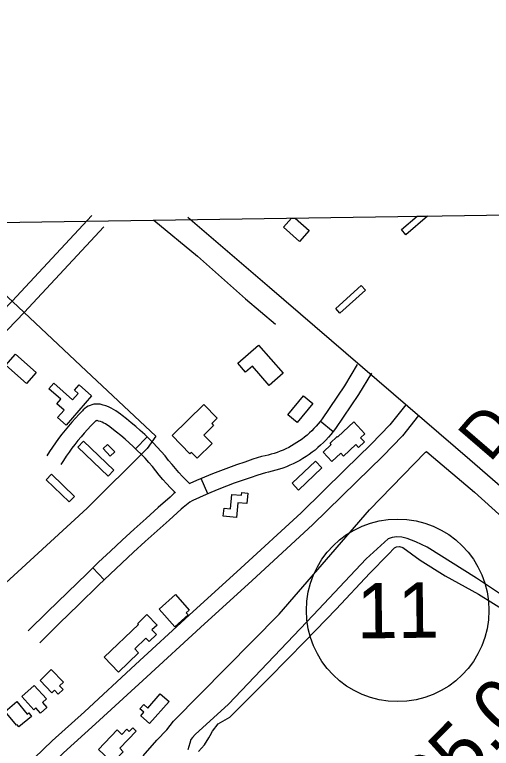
# Model space of a CAD drawing. Extents: x 3823584 to 3861785, y 301729 to 327625.
# Drawn here: x 3835049 to 3835911, y 324501 to 325827 of the extents above; entities that cross this region are included whole.
import ezdxf

# ---------------------------------------------------------------- set-up
doc = ezdxf.new("R2010")
doc.units = 0
for name, color, linetype in [('V-BLDG-OTLN', 7, 'Continuous'), ('V-GRID-FRAM', 7, 'Continuous'), ('V-RIVR-RANG-IDEN', 7, 'Continuous'), ('V-ROAD-CNTR', 7, 'Continuous'), ('V-ROAD-IDEN', 7, 'Continuous'), ('V-SITE-OTLN', 7, 'Continuous'), ('V-SITE-VEGE', 7, 'Continuous'), ('V-SURV-IDEN', 7, 'Continuous'), ('V-TOPO-SHOR', 7, 'Continuous')]:
    doc.layers.add(name, color=color, linetype=linetype)

msp = doc.modelspace()

# ---------------------------------------------------------------- linework, layer by layer
at = {"layer": 'V-BLDG-OTLN'}
for p, q in [((3835534.9, 325442.9), (3835549.4, 325459.3)), ((3835549.4, 325459.3), (3835556, 325459.4)), ((3835556, 325459.4), (3835581.4, 325437)), ((3835748, 325438.5), (3835776.3, 325462.8)), ((3835795, 325463.1), (3835755.9, 325429.4)), ((3835776.3, 325462.8), (3835795, 325463.1)), ((3835563.9, 325417.2), (3835534.9, 325442.9)), ((3835581.4, 325437), (3835563.9, 325417.2)), ((3835755.9, 325429.4), (3835748, 325438.5))]:
    msp.add_line(p, q, dxfattribs=at)
for points in [[(3835682.9, 325329), (3835636.9, 325287.6), (3835629.3, 325296), (3835675.3, 325337.5)], [(3835489.9, 325229.7), (3835534.2, 325179), (3835509.1, 325157.1), (3835479, 325191.6), (3835466.5, 325180.7), (3835452.4, 325196.9)], [(3835050.7, 325213.5), (3835088.1, 325180.5), (3835070.2, 325160.3), (3835032.9, 325193.4)], [(3835188.1, 325138.2), (3835141.8, 325085.4), (3835126.6, 325098.7), (3835138.3, 325112.1), (3835125.2, 325123.6), (3835132.4, 325131.9), (3835110.8, 325150.8), (3835119.6, 325160.9), (3835153.7, 325131), (3835163.7, 325142.5), (3835157.1, 325148.2), (3835165.6, 325157.9)], [(3835588.2, 325124.3), (3835559.7, 325089.7), (3835542.9, 325103.6), (3835571.4, 325138.1)], [(3835333.5, 325066.6), (3835391.1, 325122.3), (3835415.1, 325097.6), (3835405.1, 325088), (3835408.7, 325084.3), (3835391.2, 325067.3), (3835406, 325052), (3835378.6, 325025.4), (3835368.6, 325035.7), (3835365.9, 325033.1)], [(3835661.8, 325091), (3835682.1, 325069.6), (3835674.4, 325062.3), (3835681.3, 325055.1), (3835670.4, 325044.7), (3835665.5, 325049.9), (3835643.6, 325029.2), (3835638.5, 325034.6), (3835622.6, 325019.6), (3835606.6, 325036.5), (3835621.1, 325050.2), (3835619.2, 325052.3), (3835632.2, 325064.6), (3835633, 325063.8)], [(3835173.3, 325056.2), (3835228.5, 325003.7), (3835218.3, 324992.9), (3835163, 325045.4)], [(3835217, 325050.4), (3835229.8, 325036.7), (3835221.7, 325029.2), (3835209, 325042.9)], [(3835604.4, 325008.1), (3835562, 324967.9), (3835550.5, 324980), (3835593, 325020.3)], [(3835115.3, 324996.5), (3835157, 324956.4), (3835147.5, 324946.5), (3835105.7, 324986.6)], [(3835470.3, 324962.2), (3835468.5, 324943.3), (3835452.7, 324944.8), (3835450.2, 324918.4), (3835426, 324920.6), (3835427.4, 324934.9), (3835439.4, 324933.8), (3835441.8, 324959.9), (3835459, 324958.3), (3835459.5, 324963.2)], [(3835339.6, 324778.9), (3835364.7, 324750.9), (3835359.3, 324746), (3835362.7, 324742.1), (3835338.7, 324720.7), (3835310.2, 324752.6)], [(3835273.1, 324673.5), (3835236.8, 324638.9), (3835211, 324665.9), (3835272.9, 324725.1), (3835271.4, 324726.7), (3835288.2, 324742.8), (3835306.3, 324723.9), (3835297.2, 324715.3), (3835305.3, 324706.8), (3835291.9, 324694), (3835286.3, 324699.9), (3835266.2, 324680.7)], [(3835115.2, 324643.4), (3835137.1, 324620.8), (3835130.3, 324614.3), (3835136.7, 324607.6), (3835127.9, 324599), (3835121.1, 324606), (3835116.4, 324601.5), (3835094.8, 324623.7)], [(3835084.4, 324614.8), (3835106.3, 324590.6), (3835099, 324584), (3835107.2, 324574.9), (3835095.9, 324564.7), (3835087.5, 324574.1), (3835083.8, 324570.8), (3835062.2, 324594.6)], [(3835328, 324585.4), (3835292.5, 324545.7), (3835276.8, 324559.8), (3835282.5, 324566.2), (3835275.2, 324572.7), (3835282.2, 324580.5), (3835289.5, 324573.9), (3835312.3, 324599.4)], [(3835053.2, 324585.4), (3835071.7, 324562.9), (3835074.3, 324565.1), (3835079.6, 324558.7), (3835056.7, 324539.9), (3835053.6, 324543.6), (3835052.6, 324542.8), (3835031.9, 324567.9)], [(3835200.4, 324499.1), (3835234.1, 324534.2), (3835242.5, 324526.1), (3835251.8, 324535.8), (3835256.1, 324531.6), (3835262.3, 324538), (3835268.6, 324532), (3835238.9, 324501.1), (3835245.4, 324494.8), (3835230.8, 324479.7), (3835224.6, 324485.7), (3835219.7, 324480.6)]]:
    msp.add_lwpolyline(points, close=True, dxfattribs=at)
at = {"layer": 'V-GRID-FRAM'}
msp.add_lwpolyline([(3827552.2, 325336), (3859397.3, 325827), (3859685.5, 307646.8), (3827824.6, 307155.6), (3827552.2, 325336)], dxfattribs=at)
at = {"layer": 'V-ROAD-CNTR'}
for p, q in [((3835624.6, 325073.2), (3835601.3, 325092.1)), ((3835267.7, 325042.4), (3835288.4, 325064.1)), ((3835398, 324960.9), (3835386.2, 324988.5)), ((3835211, 324805.6), (3835190.2, 324827.2))]:
    msp.add_line(p, q, dxfattribs=at)
for points in [[(3835188.4, 325464.1), (3835044.2, 325309.3), (3834969.1, 325232), (3834950.1, 325209.7)], [(3835362.2, 325460.9), (3835509.5, 325334.3), (3835871.8, 325022.8), (3836108.4, 324817.6), (3836414, 324556.9), (3836839.8, 324193.7), (3837163.7, 323918.8), (3837445, 323669.4), (3837836.5, 323328.4), (3838069.6, 323134.9), (3838125.4, 323086.8), (3838256, 322989.5), (3838600, 322735.4), (3839019.3, 322425.4), (3839565.5, 322022.9), (3840024.9, 321675.2), (3840474.9, 321350), (3840728.4, 321161.3)], [(3835210.4, 325443.7), (3835066, 325288.6), (3834991.3, 325211.8), (3834963.4, 325179), (3834930.6, 325140.4)], [(3835668.4, 325194.8), (3835645.4, 325156.5), (3835604.6, 325096.4), (3835601.2, 325092), (3835597.6, 325087.5), (3835593.9, 325083.2), (3835590, 325079), (3835586, 325075), (3835581.9, 325071), (3835577.6, 325067.2), (3835573.2, 325063.6), (3835568.7, 325060.1), (3835564.1, 325056.8), (3835559.3, 325053.6), (3835554.5, 325050.5), (3835549.6, 325047.7), (3835544.6, 325045), (3835539.4, 325042.4), (3835534.2, 325040.1), (3835529, 325037.9), (3835523.6, 325035.9), (3835518.2, 325034), (3835512.8, 325032.4), (3835507.3, 325030.9), (3835501.7, 325029.6), (3835495.1, 325028.3), (3835479.6, 325023.4), (3835464.8, 325018.5), (3835450.2, 325013.5), (3835435.6, 325008.2), (3835421, 325002.7), (3835406.6, 324997), (3835392.2, 324991.1), (3835377.9, 324985), (3835365.4, 324979.4)], [(3835694.1, 325179.3), (3835670.7, 325140.3), (3835629, 325078.9), (3835624.9, 325073.5), (3835620.6, 325068.3), (3835616.3, 325063.2), (3835611.7, 325058.3), (3835607, 325053.5), (3835602.1, 325048.9), (3835597.1, 325044.5), (3835592, 325040.2), (3835586.7, 325036.1), (3835581.3, 325032.2), (3835575.7, 325028.4), (3835570, 325024.9), (3835564.2, 325021.5), (3835558.3, 325018.3), (3835552.3, 325015.3), (3835546.2, 325012.6), (3835540.1, 325010), (3835533.8, 325007.6), (3835527.5, 325005.5), (3835521, 325003.5), (3835514.6, 325001.8), (3835508.1, 325000.2), (3835502.5, 324999.1), (3835488.8, 324994.8), (3835474.4, 324990.1), (3835460.2, 324985.2), (3835445.9, 324980.1), (3835431.8, 324974.7), (3835417.8, 324969.2), (3835403.8, 324963.4), (3835389.9, 324957.5), (3835376.2, 324951.4), (3835372.5, 324949.7), (3835369.9, 324948.2), (3835365.8, 324945.8), (3835362.6, 324943.7), (3835359.5, 324941.4), (3835356.5, 324938.9), (3835353.6, 324936.3), (3835350.2, 324933), (3835328.1, 324913.6), (3835306.5, 324894.4), (3835285.1, 324874.9), (3835263.7, 324855.4), (3835242.6, 324835.6), (3835221.5, 324815.7), (3835200.6, 324795.7), (3835165.1, 324761.2), (3835129.6, 324726.6), (3835094.3, 324691.8)], [(3835756.2, 325122.1), (3835727.3, 325085.6), (3835693.5, 325050.5), (3835646, 325004.3), (3835566.9, 324926.9), (3835457.9, 324826.8), (3835364.5, 324741.6), (3835267.6, 324652.3), (3835175, 324567.3), (3835116.6, 324514.7), (3835068.4, 324468.3), (3835029.1, 324429.5)], [(3835365.7, 324979.1), (3835359.1, 324985.6), (3835352.5, 324992.5), (3835346, 324999.6), (3835339.6, 325006.7), (3835333.4, 325014), (3835327.3, 325021.4), (3835321.1, 325029.4), (3835313.9, 325037.6), (3835306.7, 325045.6), (3835299.3, 325053.4), (3835291.7, 325061), (3835284, 325068.4), (3835276, 325075.6), (3835268, 325082.7), (3835259.7, 325089.6), (3835251.3, 325096.3), (3835243.3, 325102.4), (3835240.2, 325105.1), (3835236.2, 325108.1), (3835232.1, 325111), (3835227.8, 325113.6), (3835223.3, 325115.9), (3835218.7, 325118), (3835214, 325119.9), (3835209.2, 325121.4), (3835203.7, 325122.9), (3835199.6, 325123.3), (3835196, 325123.3), (3835192.3, 325122.9), (3835188.7, 325122.1), (3835185.2, 325120.9), (3835181.9, 325119.4), (3835178.7, 325117.5), (3835175.8, 325115.3), (3835173.1, 325112.8), (3835171.5, 325111), (3835165.3, 325104.7), (3835158.7, 325097.8), (3835152.3, 325090.7), (3835146.1, 325083.6), (3835140, 325076.2), (3835134.1, 325068.7), (3835128.4, 325061.1), (3835122.8, 325053.4), (3835117.4, 325045.6), (3835112.2, 325037.6), (3835107.2, 325029.6)], [(3835779, 325102.6), (3835749.9, 325065.8), (3835714.7, 325029.3), (3835667, 324982.8), (3835587.5, 324905.1), (3835478.1, 324804.6), (3835384.7, 324719.5), (3835287.9, 324630.2), (3835195.1, 324545.1), (3835137, 324492.7), (3835089.4, 324446.8), (3835050.1, 324408.2)], [(3835339.6, 324962.8), (3835337.7, 324964.6), (3835330.6, 324972), (3835323.7, 324979.4), (3835317, 324987), (3835310.3, 324994.8), (3835303.9, 325002.7), (3835297.9, 325010.3), (3835291.5, 325017.7), (3835284.7, 325025.2), (3835277.8, 325032.4), (3835270.7, 325039.5), (3835263.4, 325046.5), (3835256, 325053.3), (3835248.5, 325059.9), (3835240.8, 325066.3), (3835232.9, 325072.6), (3835224.4, 325079.1), (3835221.2, 325081.8), (3835218.6, 325083.9), (3835215.8, 325085.7), (3835213, 325087.5), (3835210, 325089), (3835207, 325090.4), (3835203.9, 325091.6), (3835200.8, 325092.6), (3835198.3, 325093.3), (3835198.2, 325093.3), (3835197.7, 325093.3), (3835197.2, 325093.2), (3835196.7, 325093.1), (3835196.3, 325093), (3835195.8, 325092.8), (3835195.4, 325092.5), (3835195, 325092.3), (3835194.7, 325091.9), (3835193.5, 325090.6), (3835186.8, 325083.8), (3835180.7, 325077.4), (3835174.8, 325070.8), (3835169, 325064.2), (3835163.3, 325057.3), (3835157.8, 325050.4), (3835152.5, 325043.3), (3835147.3, 325036.1), (3835142.3, 325028.8), (3835137.5, 325021.4), (3835132.7, 325013.8)], [(3835339.3, 324963.7), (3835336.9, 324961.7), (3835333, 324958.2), (3835329.8, 324955), (3835308.2, 324936.1), (3835286.5, 324916.7), (3835264.8, 324897.1), (3835243.4, 324877.4), (3835222, 324857.5), (3835200.8, 324837.5), (3835179.8, 324817.3), (3835144.2, 324782.7), (3835108.6, 324748), (3835073.3, 324713.2)]]:
    msp.add_lwpolyline(points, dxfattribs=at)
at = {"layer": 'V-ROAD-IDEN'}
msp.add_circle((3835741.3, 324750.4), 165, dxfattribs=at)
msp.add_circle((3835741.3, 324750.4), 165, dxfattribs=at)
at = {"layer": 'V-SITE-OTLN'}
for p, q in [((3834970.6, 325377.4), (3835055.1, 325298.9)), ((3835055.1, 325298.9), (3835168.6, 325192.6)), ((3835168.6, 325192.6), (3835304.4, 325065.5)), ((3835304.4, 325065.5), (3835288.5, 325042.9)), ((3835288.5, 325042.9), (3835180.1, 324935.3)), ((3835180.1, 324935.3), (3834902.9, 324681.5))]:
    msp.add_line(p, q, dxfattribs=at)
at = {"layer": 'V-SITE-VEGE'}
for points in [[(3835281.1, 324487.3), (3835306, 324515.9), (3835324.1, 324534.2), (3835336.3, 324550.3), (3835526.9, 324743.3), (3835690.3, 324931.8), (3835791.9, 325036.3), (3835793.4, 325037.7), (3835798.5, 325033.1), (3835880, 324963.8), (3836049.6, 324811), (3836218.5, 324659.8), (3836294.2, 324599.8), (3836295.4, 324593.3), (3836272, 324574.7), (3836209.3, 324530.9), (3836201, 324534.9), (3836182.5, 324551.9), (3836060.6, 324674.6), (3835941.4, 324770.2), (3835883.6, 324808.6), (3835794.4, 324864.4)], [(3835794.4, 324864.4), (3835774.2, 324874.2), (3835758.8, 324880.5), (3835748.7, 324882.8), (3835739.8, 324883.3), (3835731.6, 324882), (3835723.9, 324879.5), (3835684.1, 324843.7), (3835588.3, 324741.6), (3835435.3, 324581), (3835375, 324525.9)], [(3835375, 324525.9), (3835370.6, 324520.8), (3835367.7, 324516.9), (3835365.4, 324510.1), (3835361.9, 324498.4)]]:
    msp.add_lwpolyline(points, dxfattribs=at)
at = {"layer": 'V-TOPO-SHOR'}
for points in [[(3835300.4, 325455.5), (3835379.2, 325390.7), (3835466.5, 325313.4), (3835520.4, 325267.8)], [(3835416.7, 324545.3), (3835437.7, 324557.3), (3835508.5, 324627.9), (3835574.8, 324695.3), (3835630.3, 324752.8), (3835691.3, 324817.4), (3835724, 324851.6), (3835735.4, 324863.6), (3835739.2, 324865.1), (3835744.6, 324865.7), (3835750.9, 324863.8), (3835782.3, 324840.9), (3835827.3, 324812.9), (3835887.7, 324779.7), (3835941.4, 324745.9), (3835987.3, 324712.9), (3836044.8, 324670.3), (3836094.4, 324631.8), (3836108.3, 324620.7), (3836123.3, 324605.7), (3836142.8, 324582.6), (3836169.1, 324546.8), (3836194, 324524.2)], [(3835381.5, 324495.4), (3835392, 324507.4), (3835399.7, 324519.8), (3835402.3, 324524.3), (3835406.8, 324532.2), (3835416.7, 324545.3)]]:
    msp.add_lwpolyline(points, dxfattribs=at)

# ---------------------------------------------------------------- texts
at = {"layer": 'V-RIVR-RANG-IDEN'}
msp.add_text('D-080', height=83, rotation=49.2643, dxfattribs=at).set_placement((3835907.8, 325015.9))
at = {"layer": 'V-ROAD-IDEN'}
msp.add_text('11', height=100, rotation=0.6162, dxfattribs=at).set_placement((3835667.8, 324699.6))
at = {"layer": 'V-SURV-IDEN'}
msp.add_text('799+05.0', height=100, rotation=45.4575, dxfattribs=at).set_placement((3835596.2, 324168.1))

doc.saveas('drawing.dxf')
